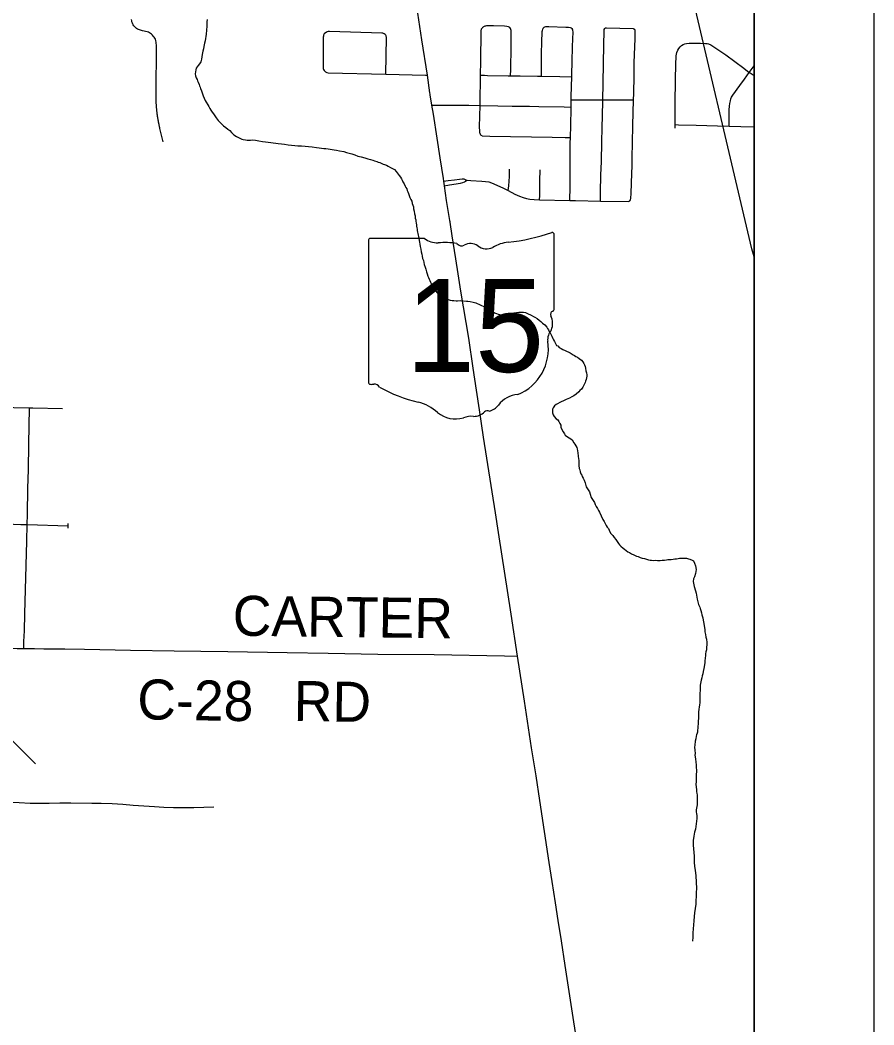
# Model space of a CAD drawing. Extents: x -483 to 680, y 0 to 440.
# Drawn here: x 333.5 to 394.1, y 248.8 to 320.1 of the extents above; entities that cross this region are included whole.
import ezdxf

# ---------------------------------------------------------------- set-up
doc = ezdxf.new("R2010")
doc.units = 0
for name, color, linetype in [('GM_X_City_Street', 7, 'Continuous'), ('GM_X_County_Road', 7, 'Continuous'), ('GM_X_County_Road_Text', 7, 'Continuous'), ('GM_X_Minor_River', 7, 'Continuous'), ('GM_X_Rail_Line', 7, 'Continuous'), ('GM_X_State_Location', 7, 'Continuous'), ('GM_X_State_Route', 7, 'Continuous'), ('GM_X_State_Shield', 7, 'Continuous'), ('SH_Cut_Line', 7, 'Continuous'), ('SH_Text', 7, 'Continuous')]:
    doc.layers.add(name, color=color, linetype=linetype)

msp = doc.modelspace()

# ---------------------------------------------------------------- linework, layer by layer
at = {"layer": 'GM_X_City_Street'}
for p, q in [((385.608, 316.112), (385.262, 316.354)), ((372.628, 313.895), (372.637, 314.413)), ((370.398, 307.331), (372.54, 307.277)), ((374.715, 307.229), (376.668, 307.209))]:
    msp.add_line(p, q, dxfattribs=at)
for points in [[(343.702, 311.432), (343.463, 312.389), (343.455, 312.422), (343.448, 312.455), (343.44, 312.488), (343.432, 312.521), (343.425, 312.554), (343.418, 312.587), (343.41, 312.62), (343.403, 312.653), (343.396, 312.686), (343.389, 312.719), (343.382, 312.752), (343.376, 312.785), (343.369, 312.818), (343.363, 312.851), (343.356, 312.884), (343.35, 312.917), (343.344, 312.951), (343.338, 312.984), (343.332, 313.017), (343.326, 313.05), (343.321, 313.084), (343.315, 313.117), (343.31, 313.15), (343.304, 313.184), (343.299, 313.217), (343.294, 313.25), (343.289, 313.284), (343.285, 313.317), (343.28, 313.35), (343.275, 313.384), (343.271, 313.418), (343.267, 313.451), (343.262, 313.484), (343.258, 313.518), (343.254, 313.551), (343.25, 313.585), (343.247, 313.619), (343.243, 313.652), (343.239, 313.686), (343.236, 313.719), (343.233, 313.753), (343.23, 313.786), (343.226, 313.82), (343.224, 313.853), (343.221, 313.887), (343.218, 313.921), (343.216, 313.954), (343.213, 313.988), (343.211, 314.022), (343.209, 314.055), (343.207, 314.089), (343.205, 314.123), (343.203, 314.157), (343.201, 314.19), (343.199, 314.224), (343.198, 314.258), (343.197, 314.291), (343.195, 314.325), (343.194, 314.359), (343.194, 314.393), (343.193, 314.426), (343.192, 314.46), (343.191, 314.494), (343.191, 314.528), (343.19, 314.561), (343.19, 314.595), (343.19, 314.629), (343.19, 314.662), (343.19, 314.696), (343.19, 314.73), (343.19, 314.764), (343.191, 314.798), (343.191, 314.831), (343.22, 318.248), (343.203, 318.489), (343.169, 318.633), (343.138, 318.712), (343.096, 318.792), (343.044, 318.869), (342.992, 318.937), (342.941, 318.997), (342.867, 319.065), (342.8, 319.116), (342.723, 319.168), (342.639, 319.21), (342.562, 319.24), (342.235, 319.317), (342.019, 319.376), (341.939, 319.401), (341.871, 319.427), (341.799, 319.474), (341.735, 319.535), (341.62, 319.653), (341.568, 319.725), (341.534, 319.794), (341.504, 319.857), (341.478, 319.948), (341.461, 320.019), (341.453, 320.11)], [(366.207, 316.16), (366.219, 317.161), (366.251, 319.26), (366.256, 319.346), (366.269, 319.399), (366.283, 319.448), (366.315, 319.504)], [(368.329, 316.119), (368.343, 316.561), (368.375, 318.17), (368.387, 318.943), (368.383, 319.322), (368.362, 319.413), (368.336, 319.469), (368.277, 319.538), (368.199, 319.586), (368.08, 319.62), (367.894, 319.637), (367.117, 319.659), (366.616, 319.653), (366.559, 319.645), (366.512, 319.636), (366.469, 319.621), (366.424, 319.604), (366.386, 319.581), (366.352, 319.548), (366.315, 319.504)], [(370.517, 316.088), (370.521, 316.437), (370.536, 317.737), (370.55, 318.483), (370.576, 319.254), (370.589, 319.342), (370.618, 319.425), (370.654, 319.505), (370.711, 319.562), (370.773, 319.595), (370.847, 319.608), (370.923, 319.614), (371.045, 319.612), (372.255, 319.579), (372.438, 319.567), (372.552, 319.545), (372.627, 319.515), (372.687, 319.467), (372.729, 319.397)], [(372.671, 316.048), (372.674, 316.24), (372.702, 317.11), (372.733, 318.198), (372.763, 319.249), (372.754, 319.332), (372.729, 319.397)], [(374.875, 314.426), (374.899, 315.579), (374.925, 317.007), (374.957, 318.279), (374.971, 319.334), (374.985, 319.414), (375.02, 319.481), (375.054, 319.512), (375.095, 319.529), (375.147, 319.534), (377.019, 319.472), (377.064, 319.46), (377.106, 319.43)], [(377.062, 314.41), (377.075, 314.873), (377.1, 316.117), (377.112, 317.05), (377.161, 318.759), (377.167, 319.287), (377.163, 319.348), (377.141, 319.393), (377.106, 319.43)], [(359.485, 316.234), (359.525, 318.834), (359.503, 318.947), (359.477, 319.011), (359.436, 319.061), (359.361, 319.109), (359.28, 319.143), (359.199, 319.155), (355.482, 319.257), (355.401, 319.252), (355.326, 319.231), (355.26, 319.202), (355.196, 319.159), (355.115, 319.087), (355.072, 319.011), (355.057, 318.939), (355.051, 318.87), (355.03, 316.679), (355.047, 316.605), (355.068, 316.556), (355.103, 316.501), (355.128, 316.464), (355.195, 316.407), (355.252, 316.368), (355.308, 316.35), (355.399, 316.34), (359.485, 316.234), (362.3, 316.162), (362.407, 316.159)], [(380.002, 312.402), (380.001, 312.656), (380.004, 314.118), (380.031, 315.882), (380.053, 316.907), (380.078, 317.53), (380.093, 317.658), (380.125, 317.782), (380.19, 317.934), (380.282, 318.068), (380.36, 318.173), (380.456, 318.264), (380.568, 318.336), (380.689, 318.388), (380.816, 318.421), (381.007, 318.441), (381.818, 318.437), (382.161, 318.419), (382.29, 318.404), (382.386, 318.378), (382.534, 318.311), (382.83, 318.132), (383.6, 317.603), (384.872, 316.658), (385.262, 316.354)], [(383.837, 312.547), (383.84, 312.83), (383.85, 313.701), (383.865, 313.976), (383.893, 314.156), (383.932, 314.356), (383.965, 314.488), (384.014, 314.611), (384.097, 314.743), (384.596, 315.426), (384.922, 315.88), (385.262, 316.354), (385.608, 316.836)], [(366.177, 314.014), (366.182, 314.456), (366.203, 315.824), (366.207, 316.16)], [(366.207, 316.16), (366.491, 316.155), (366.708, 316.151), (368.167, 316.12), (368.329, 316.119)], [(368.329, 316.119), (369.005, 316.112), (370.247, 316.092), (370.517, 316.088)], [(370.517, 316.088), (371.83, 316.068), (372.671, 316.048)], [(372.637, 314.413), (372.641, 314.655), (372.671, 316.048)], [(372.637, 314.413), (373.019, 314.42), (373.913, 314.423), (374.875, 314.426)], [(374.715, 307.229), (374.724, 307.852), (374.746, 309.089), (374.775, 310.021), (374.808, 311.451), (374.827, 312.411), (374.872, 314.274), (374.875, 314.426)], [(374.875, 314.426), (375.728, 314.415), (376.602, 314.415), (377.062, 314.41)], [(376.668, 307.209), (376.758, 307.223), (376.803, 307.252), (376.848, 307.316), (376.875, 307.424), (376.893, 307.789), (376.937, 309.185), (376.952, 309.745), (376.96, 310.336), (376.987, 311.361), (377.01, 312.605), (377.062, 314.41)], [(362.737, 314.035), (363.142, 314.035), (364.359, 314.031), (365.367, 314.028), (366.177, 314.014)], [(366.316, 311.862), (366.264, 311.882), (366.221, 311.922), (366.192, 311.969), (366.166, 312.02), (366.153, 312.072), (366.143, 312.19), (366.139, 312.498), (366.177, 314.014)], [(366.177, 314.014), (367.419, 313.989), (368.444, 313.978), (369.687, 313.958), (370.34, 313.95), (372.143, 313.909), (372.628, 313.895)], [(372.585, 311.734), (372.61, 312.604), (372.627, 313.816), (372.628, 313.895)], [(380.001, 312.656), (380.248, 312.65), (381.492, 312.617), (383.017, 312.574), (383.837, 312.547), (384.667, 312.519), (385.608, 312.49)], [(366.316, 311.862), (366.875, 311.835), (371.295, 311.758), (372.198, 311.746), (372.585, 311.734)], [(372.54, 307.277), (372.551, 308.242), (372.554, 309.154), (372.552, 309.962), (372.573, 311.334), (372.585, 311.734)], [(368.155, 307.984), (368.202, 308.313), (368.26, 308.987), (368.266, 309.51)], [(370.398, 307.331), (370.402, 307.628), (370.415, 308.662), (370.434, 309.445)], [(363.574, 308.648), (363.909, 308.694), (364.346, 308.754), (364.72, 308.8), (364.895, 308.819), (365.023, 308.811), (365.121, 308.778), (365.22, 308.721)], [(363.622, 308.324), (363.993, 308.384), (364.778, 308.511), (364.941, 308.544), (365.06, 308.593), (365.138, 308.651), (365.22, 308.721)], [(365.22, 308.721), (365.515, 308.706), (366.299, 308.658), (366.55, 308.634), (366.799, 308.591), (366.983, 308.54), (367.781, 308.179), (368.155, 307.984)], [(368.155, 307.984), (368.635, 307.734), (368.972, 307.582), (369.23, 307.486), (369.467, 307.423), (369.707, 307.378), (370.014, 307.34), (370.398, 307.331)], [(372.54, 307.277), (372.931, 307.268), (374.715, 307.229)], [(327.923, 292.704), (329.958, 292.639), (331.166, 292.627), (331.296, 292.626), (333.099, 292.588), (334.218, 292.573), (334.436, 292.57), (336.549, 292.536)], [(333.797, 275.499), (333.816, 276), (333.846, 276.745), (333.873, 277.956), (333.962, 281.401), (334.009, 283.108), (334.046, 284.288), (334.066, 285.002), (334.098, 286.865), (334.127, 288.168), (334.172, 290), (334.218, 292.573)], [(327.748, 284.539), (328.132, 284.524), (329.623, 284.465), (330.986, 284.406), (331.457, 284.385), (333.601, 284.305), (334.046, 284.288), (336.954, 284.211)], [(336.957, 284.033), (336.954, 284.211), (336.956, 284.379)], [(327.363, 270.222), (327.903, 270.223), (328.173, 270.223), (329.119, 270.225), (330.149, 270.226), (330.53, 270.226), (330.948, 270.221), (331.116, 270.211), (331.241, 270.196), (331.383, 270.171), (331.519, 270.138), (331.639, 270.1), (331.773, 270.044), (331.881, 269.987), (331.969, 269.929), (332.144, 269.797), (332.334, 269.617), (332.914, 269.045), (333.406, 268.551), (333.827, 268.127), (334.309, 267.648), (334.625, 267.333)]]:
    msp.add_lwpolyline(points, dxfattribs=at)
at = {"layer": 'GM_X_County_Road'}
for points in [[(330.796, 275.52), (333.33, 275.5), (333.797, 275.499)], [(333.797, 275.499), (334.57, 275.498), (335.226, 275.49)], [(335.226, 275.49), (335.273, 275.489), (336.714, 275.47), (338.111, 275.448), (341.372, 275.395), (344.477, 275.348), (346.351, 275.316)], [(346.351, 275.316), (348.283, 275.289), (352.477, 275.218), (355.397, 275.168), (358.907, 275.112), (362.915, 275.072), (367.908, 274.973), (368.805, 274.957)]]:
    msp.add_lwpolyline(points, dxfattribs=at)
at = {"layer": 'GM_X_Minor_River'}
for points in [[(346.805, 320.107), (346.8, 319.955), (346.796, 319.803), (346.791, 319.651), (346.737, 319.083), (346.713, 318.912), (346.69, 318.761), (346.666, 318.61), (346.623, 318.44), (346.601, 318.307), (346.578, 318.194), (346.554, 318.023), (346.512, 317.872), (346.489, 317.74), (346.467, 317.627), (346.443, 317.475), (346.42, 317.305), (346.398, 317.21), (346.357, 317.116), (346.258, 316.967), (346.179, 316.855), (346.1, 316.763), (346.021, 316.651), (345.998, 316.537), (345.976, 316.405), (345.972, 316.272), (345.986, 316.119), (346.039, 315.966), (346.092, 315.85), (346.128, 315.754), (346.163, 315.658), (346.234, 315.504), (346.27, 315.408), (346.305, 315.312), (346.34, 315.216), (346.411, 315.043), (346.481, 314.85), (346.534, 314.697), (346.605, 314.543), (346.676, 314.37), (346.93, 313.944), (347.002, 313.809), (347.074, 313.674), (347.165, 313.538), (347.256, 313.421), (347.347, 313.286), (347.458, 313.149), (347.531, 313.052), (347.604, 312.955), (347.733, 312.818), (347.825, 312.72), (347.973, 312.583), (348.14, 312.464), (348.289, 312.346), (348.419, 312.247), (348.528, 312.092), (348.695, 311.935), (348.881, 311.816), (349.031, 311.735), (349.125, 311.695)], [(349.125, 311.695), (349.275, 311.633), (349.369, 311.611), (349.52, 311.588), (349.653, 311.565), (349.766, 311.562), (349.88, 311.559), (350.033, 311.573), (350.241, 311.548), (350.486, 311.503), (350.732, 311.458), (350.94, 311.433), (351.148, 311.408), (351.678, 311.336), (351.849, 311.331), (352.075, 311.286), (352.303, 311.261), (352.549, 311.235), (352.795, 311.209), (353.022, 311.183), (353.249, 311.158), (353.496, 311.151), (353.761, 311.124), (354.007, 311.098), (354.253, 311.072), (354.556, 311.025), (354.745, 311.02), (354.916, 310.996), (355.086, 310.972), (355.238, 310.967), (355.389, 310.944), (355.54, 310.921), (355.672, 310.898), (355.824, 310.874), (355.994, 310.851), (356.202, 310.807), (356.504, 310.741), (356.692, 310.678), (356.88, 310.635), (357.069, 310.592), (357.276, 310.51), (357.501, 310.427), (357.746, 310.363), (357.991, 310.299), (358.198, 310.236), (358.405, 310.173), (358.575, 310.13), (358.688, 310.089), (358.838, 310.046), (358.932, 310.006), (359.064, 309.964), (359.289, 309.862), (359.383, 309.84), (359.533, 309.779), (359.646, 309.719), (359.814, 309.619), (359.963, 309.539), (360.094, 309.478), (360.223, 309.322), (360.37, 309.147), (360.443, 309.05), (360.534, 308.933), (360.607, 308.817), (360.642, 308.721), (360.696, 308.605), (360.786, 308.45), (360.858, 308.296), (360.912, 308.199), (360.966, 308.103), (361.001, 307.988), (361.055, 307.891), (361.09, 307.776), (361.143, 307.642), (361.195, 307.488), (361.267, 307.353), (361.32, 307.218), (361.354, 307.065), (361.408, 306.95), (361.442, 306.834), (361.457, 306.682), (361.49, 306.51), (361.523, 306.338), (361.556, 306.185), (361.571, 306.032), (361.605, 305.917), (361.621, 305.803), (361.636, 305.669), (361.652, 305.555), (361.668, 305.459), (361.684, 305.345), (361.7, 305.249), (361.716, 305.154), (361.732, 305.039), (361.767, 304.943), (361.782, 304.809), (361.798, 304.714), (361.863, 304.332), (361.897, 304.179), (361.93, 304.007), (361.962, 303.816), (361.995, 303.625)], [(361.995, 303.625), (362.047, 303.471), (362.062, 303.319), (362.095, 303.165), (362.148, 303.012), (362.182, 302.878), (362.216, 302.744), (362.267, 302.552), (362.32, 302.398), (362.371, 302.207), (362.425, 302.072), (362.477, 301.919), (362.512, 301.823), (362.566, 301.707), (362.601, 301.611), (362.655, 301.495), (362.709, 301.399), (362.761, 301.226), (362.871, 301.109), (362.926, 301.012), (363.017, 300.896), (363.108, 300.76), (363.237, 300.604), (363.367, 300.505), (363.497, 300.406), (363.647, 300.345), (363.816, 300.283), (363.91, 300.261), (364.042, 300.22), (364.193, 300.196), (364.307, 300.174), (364.477, 300.169), (364.572, 300.166), (364.763, 300.18), (365.198, 300.148), (365.312, 300.145), (365.463, 300.103), (365.69, 300.058), (365.784, 300.036), (365.878, 300.015), (365.972, 299.974), (366.084, 299.914), (366.178, 299.873), (366.272, 299.832), (366.384, 299.772), (366.478, 299.731), (366.646, 299.631), (366.757, 299.533), (366.944, 299.452), (367.094, 299.371), (367.206, 299.311), (367.338, 299.269), (367.45, 299.209), (367.563, 299.187), (367.696, 299.164), (367.828, 299.141), (367.96, 299.118), (368.094, 299.153), (368.209, 299.187), (368.305, 299.222), (368.44, 299.276), (368.555, 299.31), (368.745, 299.343), (368.917, 299.357), (369.031, 299.354), (369.126, 299.351), (369.258, 299.347), (369.391, 299.343), (369.541, 299.263), (369.803, 299.141), (369.972, 299.06), (370.065, 299.001), (370.214, 298.901), (370.363, 298.783), (370.474, 298.685), (370.604, 298.586), (370.771, 298.448), (370.899, 298.292), (370.953, 298.196), (371.026, 298.099), (371.08, 297.983), (371.134, 297.886), (371.206, 297.751), (371.26, 297.654), (371.331, 297.481), (371.386, 297.385), (371.439, 297.269), (371.493, 297.172), (371.583, 296.999), (371.677, 296.958), (371.788, 296.86), (371.919, 296.78), (372.049, 296.7), (372.199, 296.639), (372.312, 296.598), (372.462, 296.517), (372.556, 296.477), (372.779, 296.337), (372.873, 296.277), (372.966, 296.218), (373.078, 296.157)], [(373.078, 296.157), (373.19, 296.078), (373.357, 295.959), (373.468, 295.842), (373.521, 295.726), (373.576, 295.63), (373.629, 295.495), (373.644, 295.381), (373.677, 295.19), (373.711, 295.056), (373.745, 294.921), (373.742, 294.826), (373.719, 294.694), (373.697, 294.581), (373.656, 294.468), (373.634, 294.373), (373.574, 294.28), (373.513, 294.13), (373.453, 294.036), (373.355, 293.906), (373.256, 293.795), (373.178, 293.702), (372.983, 293.536), (372.828, 293.427), (372.674, 293.355), (372.519, 293.265), (372.385, 293.211), (372.288, 293.157), (372.192, 293.122), (371.827, 292.961), (371.672, 292.852), (371.575, 292.797), (371.459, 292.706), (371.36, 292.576), (371.319, 292.482), (371.315, 292.33), (371.312, 292.216), (371.346, 292.082), (371.418, 291.965), (371.565, 291.79), (371.677, 291.711), (371.768, 291.594), (371.84, 291.459), (371.894, 291.344), (371.909, 291.21), (371.98, 291.037), (372.07, 290.863), (372.161, 290.727), (372.215, 290.631), (372.364, 290.512), (372.494, 290.433), (372.607, 290.372), (372.699, 290.294), (372.827, 290.1), (372.881, 290.003), (372.972, 289.868), (373.044, 289.751), (373.061, 289.656), (373.076, 289.522), (373.11, 289.388), (373.14, 289.14), (373.154, 288.95), (373.17, 288.854), (373.186, 288.74), (373.181, 288.588), (373.178, 288.474), (373.21, 288.264), (373.245, 288.168), (373.26, 288.034), (373.313, 287.9), (373.387, 287.802), (373.422, 287.706), (373.476, 287.591), (373.547, 287.436), (373.618, 287.263), (373.704, 286.976), (373.831, 286.763), (373.922, 286.608), (373.974, 286.455), (374.062, 286.205), (374.189, 285.992), (374.28, 285.857), (374.333, 285.722), (374.404, 285.568), (374.495, 285.432), (374.567, 285.297), (374.639, 285.162), (374.89, 284.641), (374.962, 284.506), (375.034, 284.371), (375.106, 284.236), (375.197, 284.1), (375.271, 284.003), (375.324, 283.887), (375.433, 283.694), (375.579, 283.519), (375.689, 283.383), (375.799, 283.227), (375.89, 283.092), (375.981, 282.956), (376.073, 282.858)], [(376.073, 282.858), (376.146, 282.761), (376.313, 282.623), (376.406, 282.544), (376.536, 282.446), (376.647, 282.366), (376.779, 282.305), (376.909, 282.226), (377.078, 282.145), (377.172, 282.104), (377.265, 282.063), (377.378, 282.022), (377.528, 281.961), (377.679, 281.918), (377.83, 281.876), (377.98, 281.834), (378.112, 281.792), (378.225, 281.77), (378.339, 281.766), (378.472, 281.744), (378.624, 281.758), (378.757, 281.754), (378.946, 281.749), (379.099, 281.763), (379.251, 281.778), (379.385, 281.793), (379.499, 281.809), (379.613, 281.806), (379.727, 281.821), (379.88, 281.836), (379.995, 281.871), (380.108, 281.867), (380.223, 281.883), (380.318, 281.899), (380.679, 281.908), (380.812, 281.904), (380.963, 281.862), (381.057, 281.84), (381.207, 281.76), (381.301, 281.719), (381.372, 281.546), (381.461, 281.372), (381.492, 281.105), (381.469, 280.973), (381.445, 280.821), (381.382, 280.595), (381.302, 280.445), (381.296, 280.255), (381.362, 279.911), (381.448, 279.586), (381.5, 279.432), (381.563, 278.993), (381.667, 278.629), (381.756, 278.436), (381.791, 278.34), (381.825, 278.206), (381.877, 278.033), (381.911, 277.88), (381.962, 277.689), (381.995, 277.517), (382.029, 277.383), (382.079, 277.134), (382.093, 276.962), (382.109, 276.848), (382.123, 276.695), (382.156, 276.504), (382.188, 276.313), (382.222, 276.16), (382.253, 275.931), (382.267, 275.76), (382.243, 275.589), (382.238, 275.418), (382.196, 275.267), (382.173, 275.135), (382.169, 275.002), (382.145, 274.813), (382.12, 274.623), (382.117, 274.49), (382.094, 274.358), (382.07, 274.206), (382.047, 274.074), (382.003, 273.866), (381.961, 273.696), (381.919, 273.564), (381.896, 273.432), (381.853, 273.262), (381.786, 272.903), (381.781, 272.732), (381.775, 272.542), (381.75, 272.314), (381.763, 272.105), (381.758, 271.953), (381.755, 271.858), (381.752, 271.763), (381.749, 271.649), (381.726, 271.517), (381.721, 271.346), (381.698, 271.194), (381.673, 270.986), (381.664, 270.663), (381.66, 270.53)], [(381.66, 270.53), (381.636, 270.379), (381.63, 270.17), (381.625, 269.98), (381.621, 269.847), (381.598, 269.714), (381.594, 269.581), (381.573, 269.487), (381.531, 269.374), (381.51, 269.279), (381.466, 269.091), (381.424, 268.94), (381.42, 268.826), (381.399, 268.731), (381.396, 268.636), (381.392, 268.503), (381.405, 268.294), (381.417, 268.065), (381.414, 267.932), (381.444, 267.685), (381.475, 267.436), (381.489, 267.246), (381.503, 267.074), (381.516, 266.884), (381.513, 266.77), (381.507, 266.561), (381.492, 266.048), (381.487, 265.877), (381.5, 265.668), (381.514, 265.496), (381.528, 265.344), (381.545, 265.248), (381.559, 265.096), (381.574, 264.962), (381.57, 264.81), (381.577, 264.411), (381.51, 264.07), (381.506, 263.899), (381.522, 263.804), (381.536, 263.632), (381.549, 263.442), (381.458, 262.684)], [(330.844, 263.692), (331.407, 264.365), (332.117, 264.595), (332.82, 264.597), (333.485, 264.581), (334.245, 264.524), (334.949, 264.526), (335.614, 264.528), (336.356, 264.548), (337.137, 264.567), (338.638, 264.53), (339.304, 264.533), (340.083, 264.513), (340.823, 264.457), (341.564, 264.401), (343.082, 264.287), (343.747, 264.252), (344.431, 264.216), (345.173, 264.217), (345.857, 264.219), (346.58, 264.239), (347.285, 264.279)], [(381.458, 262.684), (381.381, 262.479), (381.341, 262.194), (381.281, 261.89), (381.296, 261.547), (381.313, 261.3), (381.329, 261.033), (381.365, 260.785), (381.36, 260.329), (381.377, 260.062), (381.431, 259.757), (381.465, 259.395), (381.499, 258.919), (381.513, 258.501), (381.51, 258.177), (381.508, 257.911), (381.486, 257.625), (381.465, 257.378), (381.424, 257.074), (381.383, 256.751), (381.361, 256.503), (381.339, 256.18), (381.318, 255.895), (381.277, 255.628), (381.255, 255.343), (381.271, 255.038), (381.25, 254.753)]]:
    msp.add_lwpolyline(points, dxfattribs=at)
at = {"layer": 'GM_X_Rail_Line'}
msp.add_lwpolyline([(385.608, 303.281), (385.452, 303.84), (380.508, 324.868), (378.064, 331.238), (375.078, 338.151), (371.617, 345.13), (361.712, 360.715), (360.22, 362.951), (358.661, 364.373), (357.034, 364.982), (355.269, 365.293)], dxfattribs=at)
at = {"layer": 'GM_X_State_Route'}
for points in [[(360.995, 325.278), (361.059, 324.873), (361.202, 323.983), (361.565, 321.587), (361.726, 320.574), (362.024, 318.67), (362.407, 316.159), (362.595, 314.921), (362.608, 314.828), (362.616, 314.779)], [(362.616, 314.779), (362.737, 314.035), (362.839, 313.408), (363.104, 311.689), (363.32, 310.309), (363.546, 308.836), (363.574, 308.648), (363.622, 308.324), (363.777, 307.27), (364.009, 305.86), (364.021, 305.788)], [(364.021, 305.788), (364.028, 305.739), (364.176, 304.782), (364.433, 303.129)], [(364.433, 303.129), (364.596, 302.078), (364.79, 300.85), (365.341, 297.505), (365.652, 295.382), (365.895, 293.815), (366.098, 292.43), (366.396, 290.494), (367.23, 285.117), (367.462, 283.737), (368.362, 277.929), (368.805, 274.957)], [(368.805, 274.957), (369.307, 271.757), (369.806, 268.469), (370.116, 266.473), (370.386, 264.721), (371.052, 260.326), (371.256, 258.975), (371.5, 257.471), (371.689, 256.211), (371.923, 254.769), (372.185, 253.016), (372.701, 249.636), (373.226, 246.289)]]:
    msp.add_lwpolyline(points, dxfattribs=at)
at = {"layer": 'GM_X_State_Shield'}
for p, q in [((358.248, 304.418), (358.248, 294.412)), ((362.239, 304.59), (358.378, 304.59)), ((371.432, 299.604), (371.432, 304.838)), ((371.43, 299.605), (371.432, 299.604))]:
    msp.add_line(p, q, dxfattribs=at)
for centre, radius, start, end in [((358.399, 304.439), 0.153, 98.1301, 188.1301), ((363.158, 305.752), 1.481, 231.61951, 271.11188), ((368.519, 301.534), 2.813, 97.34618, 120.76885), ((366.735, 318.232), 13.981, 275.84447, 288.90645), ((371.285, 304.86), 0.147, 351.86209, 97.738), ((363.649, 298.973), 5.318, 80.48669, 94.98827), ((364.857, 304.491), 0.427, 219.79206, 297.10237), ((365.484, 303.335), 0.889, 54.46668, 119.14113), ((366.631, 304.921), 1.069, 233.85621, 294.82819), ((371.398, 299.22), 0.227, 107.94398, 210.33697), ((371.275, 299.584), 0.157, 289.60381, 7.73413), ((369.953, 298.558), 1.363, 340.03296, 23.64957), ((371.957, 297.413), 0.992, 136.8065, 186.92959), ((367.519, 296.748), 3.497, 292.30889, 8.98584), ((358.401, 294.39), 0.154, 171.95839, 258.30661), ((358.424, 295.414), 1.176, 267.33899, 280.60386), ((358.665, 293.835), 0.424, 29.74838, 93.27175), ((364.018, 302.825), 10.096, 240.41292, 257.1985), ((361.008, 289.917), 3.159, 47.18416, 75.83597), ((368.993, 291.603), 1.915, 94.40312, 142.57675), ((364.424, 293.785), 2.004, 230.70037, 286.29184), ((365.729, 293.036), 1.068, 268.77702, 315.54927), ((366.695, 292.067), 0.301, 65.75173, 132.64842), ((366.567, 293.442), 1.13, 282.87319, 323.27711), ((365.582, 290.326), 1.647, 85.69512, 111.20995)]:
    msp.add_arc(centre, radius, start, end, dxfattribs=at)
at = {"layer": 'SH_Cut_Line'}
msp.add_lwpolyline([(385.608, 55.95), (385.608, 395.95), (45.608, 395.95), (45.608, 281.486), (47.873, 281.454), (57.759, 281.293), (64.783, 281.226), (67.114, 281.188), (73.333, 281.086), (75.975, 281.043), (77.151, 281.034), (77.105, 279.466), (77.065, 275.738), (77.043, 273.874), (76.996, 269.37), (76.941, 265.642), (76.868, 261.138), (76.791, 256.013), (76.689, 249.801), (76.636, 246.539)], dxfattribs=at)
at = {"layer": 'SH_Text'}
for points in [[(37.108, 404.45), (394.108, 404.45), (394.108, 47.45), (37.108, 47.45)], [(45.608, 395.95), (385.608, 395.95), (385.608, 55.95), (45.608, 55.95)]]:
    msp.add_lwpolyline(points, close=True, dxfattribs=at)

# ---------------------------------------------------------------- texts
at = {"layer": 'GM_X_County_Road_Text'}
for s, rotation, p in [('CARTER', 359.30315, (348.612, 276.414)), ('C-28', 358.97701, (341.836, 270.487)), ('RD', 359.01091, (352.931, 270.373))]:
    msp.add_text(s, height=2.8409, rotation=rotation, dxfattribs=at).set_placement(p)
at = {"layer": 'GM_X_State_Location'}
for s in ['s', 'r']:
    msp.add_text(s, height=0.00947, dxfattribs=at).set_placement((364.691, 298.75))
msp.add_text('15', height=0.00947, rotation=0.00001, dxfattribs=at).set_placement((362.307, 298.061))
at = {"layer": 'GM_X_State_Shield'}
msp.add_text('15', height=6.5918, dxfattribs=at).set_placement((360.914, 295.118))

doc.saveas('drawing.dxf')
